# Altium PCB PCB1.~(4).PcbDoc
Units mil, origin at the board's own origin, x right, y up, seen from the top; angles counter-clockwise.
Board outline 6095 x 4020 mil, 2 copper layers (Top Layer, Bottom Layer); 0 components, 0 nets, 0 pads, 0 vias.
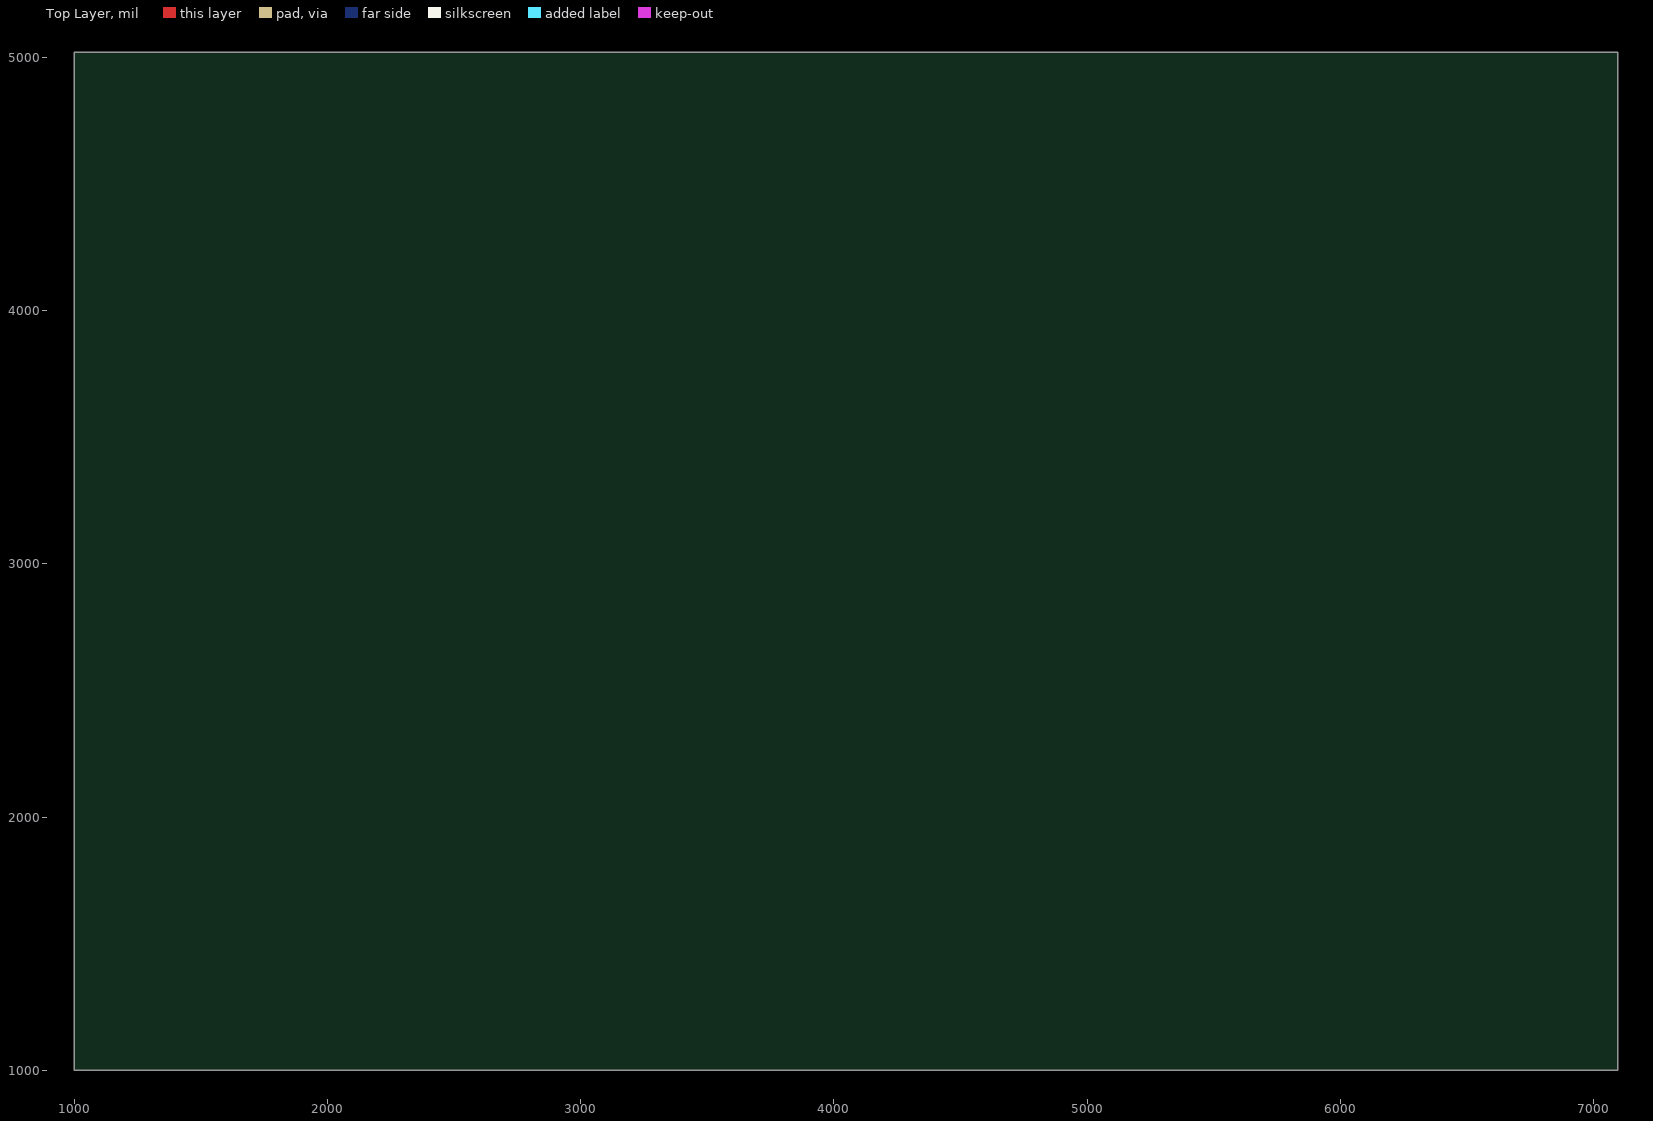
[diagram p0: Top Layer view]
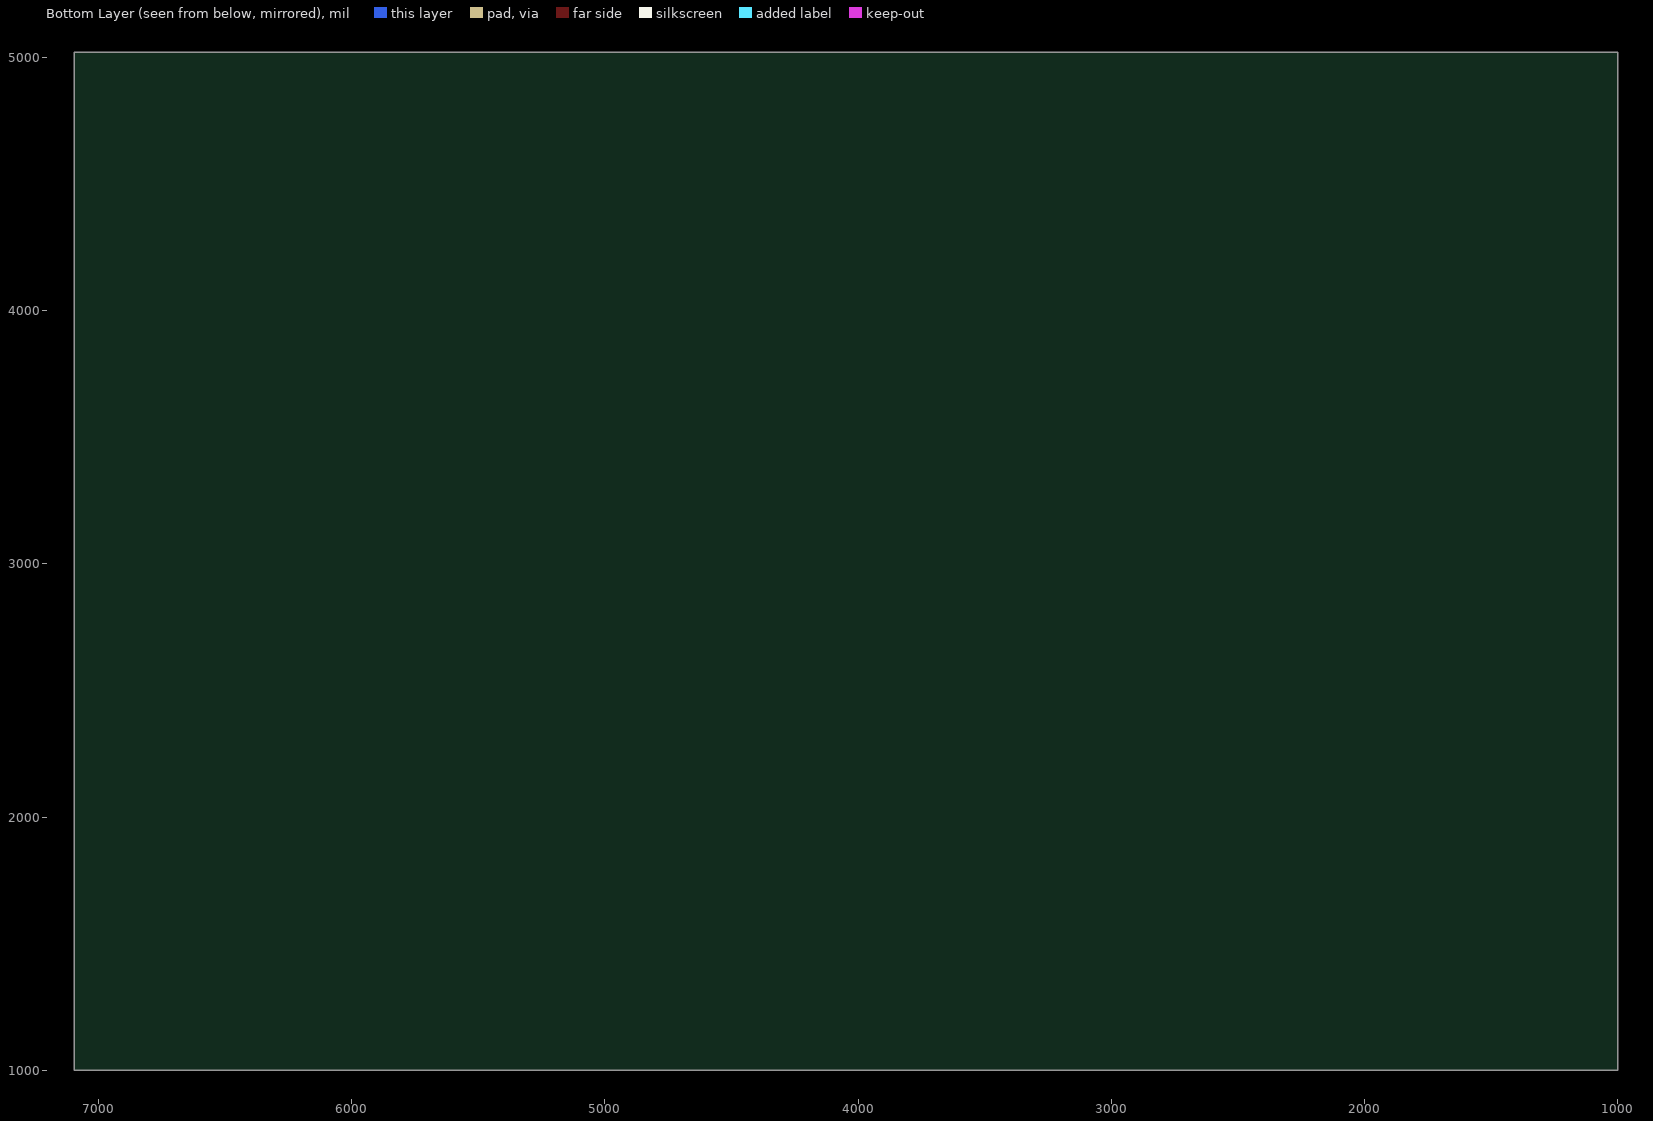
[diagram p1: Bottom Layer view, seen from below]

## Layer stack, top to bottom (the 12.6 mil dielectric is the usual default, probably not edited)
Top Solder: solder mask 0.4, Solder Resist, Dk 3.5
Top Layer: signal copper 1.4
Dielectric 1: dielectric 12.6, FR-4, Dk 4.8
Bottom Layer: signal copper 1.4
Bottom Solder: solder mask 0.4, Solder Resist, Dk 3.5

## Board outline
1000,1000 7095,1000 7095,5020 1000,5020

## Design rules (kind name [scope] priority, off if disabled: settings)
Clearance [All] p1: gap=10
PolygonConnect [All] p1: connectstyle=Relief reliefconductorwidth=10 reliefentries=4 polygonreliefangle="90 Angle" airgapwidth=10
RoutingVias [All] p1: holewidth=28 width=50 viastyle="Through Hole" minholewidth=28 minwidth=50 maxholewidth=28 maxwidth=50
SolderMaskExpansion [All] p1: expansion=4
Width [All] p1: maxlimit=10 minlimit=10 preferedwidth=10
30 further rules are at their usual default settings.

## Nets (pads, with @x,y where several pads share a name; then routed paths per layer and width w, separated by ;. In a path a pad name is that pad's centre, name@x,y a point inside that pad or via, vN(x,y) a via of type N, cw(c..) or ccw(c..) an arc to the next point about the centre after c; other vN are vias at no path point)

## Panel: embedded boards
"..\..\students\Project_LA\PCB_Project\PCB3_LA.PcbDoc" at 5125,3050, 1 rows x 1 columns, spacing 2500 x 1500, rotation 0
"..\..\students\PCB_John_Max\Project Logs for PCB_John_Max\PCB1.PcbDoc" at 5125,1000, 1 rows x 1 columns, spacing 2500 x 1500, rotation 0
"..\..\students\amplisourcecommune\PCB1.PcbDoc" at 3075,3050, 1 rows x 1 columns, spacing 2500 x 1500, rotation 0
"F:\Documents\ULB\ELECH314\2017-2018\Labo 2\students\WIWI PCB PROJECT NANA\PCB_ProjectNATAHETWILLIAM\PCB3.PcbDoc" at 1000,3050, 1 rows x 1 columns, spacing 2500 x 1500, rotation 0
"F:\Documents\ULB\ELECH314\2017-2018\Labo 2\students\MSE\PCB2.PcbDoc" at 3075,1000, 1 rows x 1 columns, spacing 2500 x 1500, rotation 0
"F:\Documents\ULB\ELECH314\2017-2018\Labo 2\students\LaboElecAnalPCB\PCB_Project_Cyp_et_Mat\PCB2.PcbDoc" at 1000,1000, 1 rows x 1 columns, spacing 2500 x 1500, rotation 0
